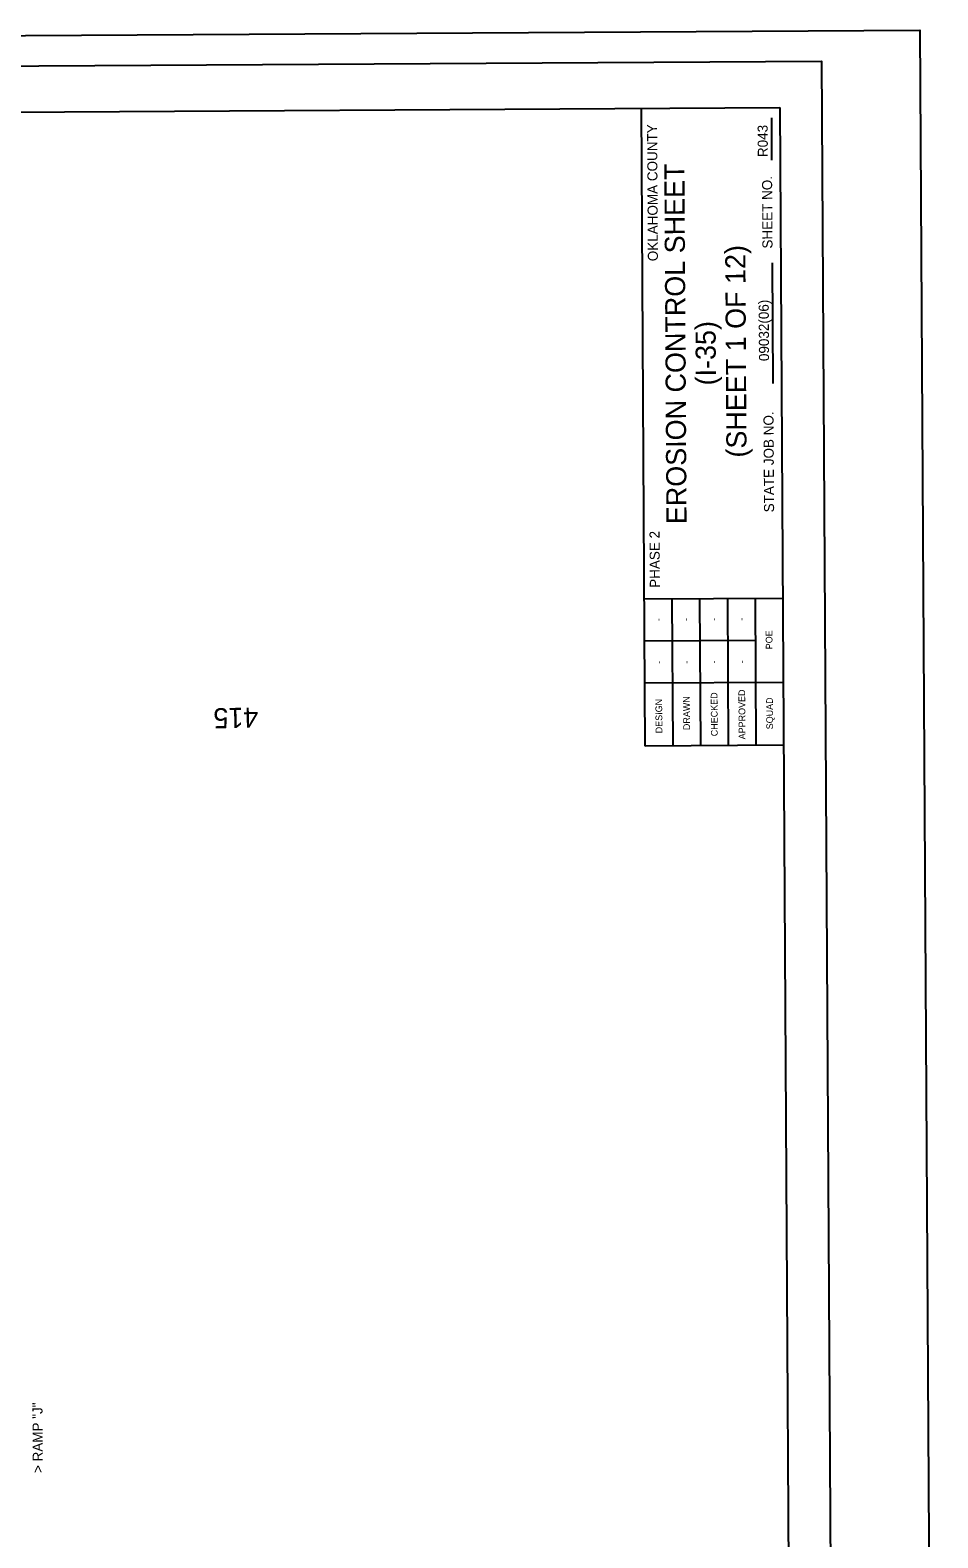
# Model space of a CAD drawing. Extents: x 2150220 to 2151431, y 143266 to 145351.
# Drawn here: x 2150890 to 2151431, y 144308 to 145206 of the extents above; entities that cross this region are included whole.
import ezdxf

# ---------------------------------------------------------------- set-up
doc = ezdxf.new("R2010")
doc.units = 0
for name, color, linetype in [('PR_Align_Ramp_H_Sta', 7, 'Continuous'), ('PR_Align_Ramp_J_Label', 7, 'Continuous'), ('SHT_Plot_Shape_Full', 7, 'Continuous'), ('SHT_Plot_Shape_Half', 7, 'Continuous'), ('SHT_Sheet_Border', 7, 'Continuous'), ('SHT_Standard_Sheet_Lines', 7, 'Continuous'), ('SHT_Standard_Sheet_Txt', 7, 'Continuous')]:
    doc.layers.add(name, color=color, linetype=linetype)

msp = doc.modelspace()

# ---------------------------------------------------------------- linework, layer by layer
at = {"layer": 'SHT_Plot_Shape_Full'}
msp.add_lwpolyline([(2150231, 143398.77), (2150220.19, 145198.73), (2151420.16, 145205.94), (2151430.98, 143405.98)], close=True, dxfattribs=at)
at = {"layer": 'SHT_Plot_Shape_Half'}
msp.add_lwpolyline([(2150271.76, 143480.89), (2150261.54, 145180.86), (2151361.52, 145187.47), (2151371.74, 143487.5)], close=True, dxfattribs=at)
at = {"layer": 'SHT_Sheet_Border'}
for p, q in [((2151256.47, 144779.33), (2151254.19, 145159.32)), ((2151338.45, 144867.32), (2151255.91, 144866.82)), ((2151338.97, 144779.82), (2151256.47, 144779.33))]:
    msp.add_line(p, q, dxfattribs=at)
msp.add_lwpolyline([(2151336.69, 145159.82), (2151346.15, 143584.85), (2150296.17, 143578.54), (2150286.71, 145153.51)], close=True, dxfattribs=at)
at = {"layer": 'SHT_Standard_Sheet_Lines'}
for p, q in [((2151332.07, 145128.56), (2151331.92, 145153.68)), ((2151332.87, 144995.33), (2151332.44, 145067.34)), ((2151322.09, 144842.22), (2151256.06, 144841.82)), ((2151338.75, 144817.32), (2151256.21, 144816.83))]:
    msp.add_line(p, q, dxfattribs=at)
for points in [[(2151272.45, 144866.92), (2151272.97, 144779.43)], [(2151288.95, 144867.02), (2151289.47, 144779.53)], [(2151305.45, 144867.12), (2151305.97, 144779.63)], [(2151321.95, 144867.22), (2151322.47, 144779.72)]]:
    msp.add_lwpolyline(points, dxfattribs=at)

# ---------------------------------------------------------------- texts
at = {"layer": 'PR_Align_Ramp_H_Sta'}
msp.add_text('415', height=12, rotation=181.16271, dxfattribs=at).set_placement((2151025.67, 144802.43))
at = {"layer": 'PR_Align_Ramp_J_Label'}
msp.add_text('> RAMP "J"', height=6, rotation=90.34413, dxfattribs=at).set_placement((2150897.34, 144346.24))
at = {"layer": 'SHT_Standard_Sheet_Txt'}
for s, height, p in [('OKLAHOMA COUNTY', 6, (2151264.07, 145068.28)), ('R043', 6, (2151329.6, 145130.33)), ('EROSION CONTROL SHEET', 12, (2151281.15, 144911.63)), ('SHEET NO. ', 6, (2151332.39, 145075.82)), ('(SHEET 1 OF 12)', 12, (2151316.92, 144951.31)), ('09032(06)', 6, (2151330.33, 145008.78)), ('(I-35)', 12, (2151298.66, 144994.29)), ('STATE JOB NO.', 6, (2151333.33, 144918.65)), ('PHASE 2', 6, (2151265.24, 144873.67)), ('-', 4, (2151266.26, 144853.83)), ('-', 4, (2151282.76, 144853.93)), ('-', 4, (2151299.27, 144854.03)), ('-', 4, (2151315.78, 144854.13)), ('POE', 4, (2151332.38, 144837.04)), ('-', 4, (2151266.41, 144828.41)), ('-', 4, (2151282.92, 144828.51)), ('-', 4, (2151299.43, 144828.61)), ('-', 4, (2151315.93, 144828.71)), ('DESIGN', 4, (2151266.68, 144787)), ('DRAWN', 4, (2151283.18, 144788.89)), ('CHECKED', 4, (2151299.71, 144785.23)), ('APPROVED', 4, (2151316.23, 144783.37)), ('SQUAD', 4, (2151332.7, 144789.36))]:
    msp.add_text(s, height=height, rotation=90.34424, dxfattribs=at).set_placement(p)

doc.saveas('drawing.dxf')
